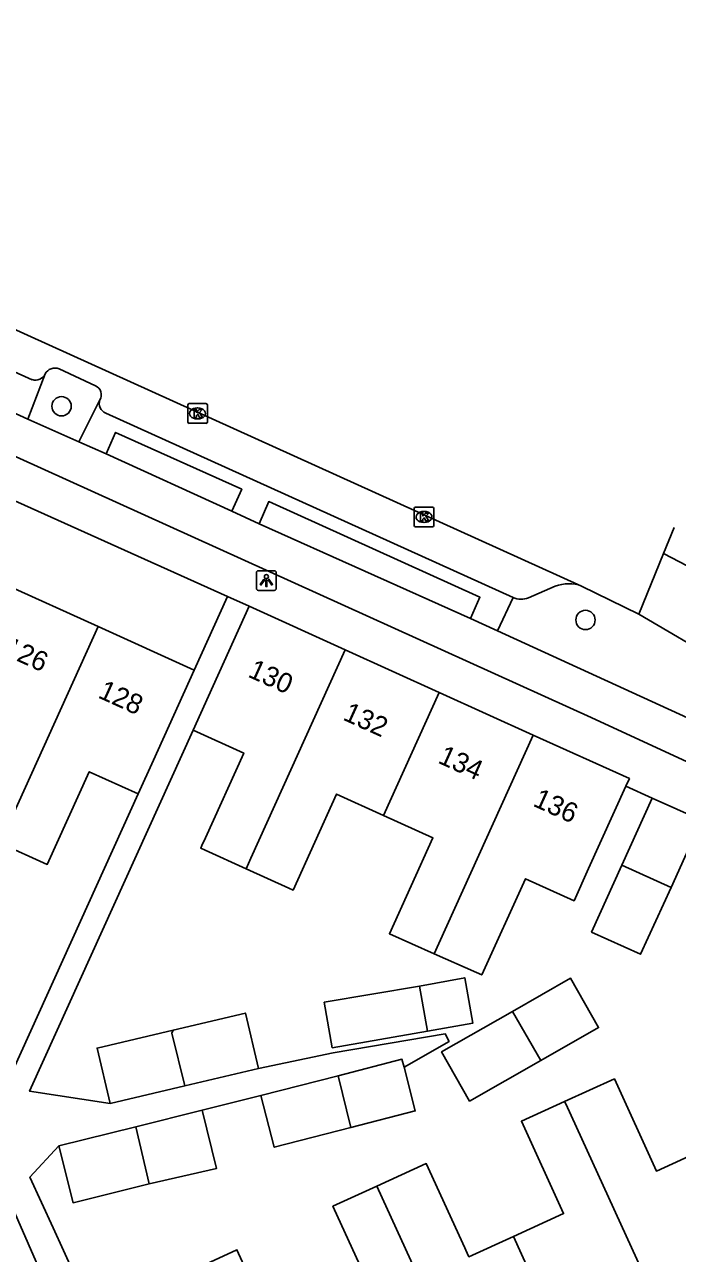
# Model space of a CAD drawing. Extents: x 161845 to 162341, y 381620 to 382158.
# Drawn here: x 162238.1 to 162271.1, y 381756.3 to 381818.5 of the extents above; entities that cross this region are included whole.
import ezdxf

# ---------------------------------------------------------------- set-up
doc = ezdxf.new("R2010")
doc.units = 0
for name, color, linetype in [('IMGEO_Boom', 7, 'Continuous'), ('IMGEO_Kolk', 7, 'Continuous'), ('IMGEO_Lichtpunt', 7, 'Continuous'), ('IMGEO_Pand', 7, 'Continuous'), ('IMGEO_Pand_nummerreeks', 7, 'Continuous'), ('IMGEO_Parkeervlak_open', 7, 'Continuous'), ('IMGEO_Rijbaan_lokaal_gesloten', 7, 'Continuous'), ('IMGEO_Voetpad_gesloten', 7, 'Continuous'), ('IMGEO_Voetpad_open', 7, 'Continuous')]:
    doc.layers.add(name, color=color, linetype=linetype)

msp = doc.modelspace()

# ---------------------------------------------------------------- linework, layer by layer
at = {"layer": 'IMGEO_Boom'}
for centre in [(162239.935, 381799.186), (162266.46, 381788.366)]:
    msp.add_circle(centre, 0.489, dxfattribs=at)
at = {"layer": 'IMGEO_Kolk'}
for p, q in [((162246.321, 381798.395), (162246.321, 381799.247)), ((162246.396, 381799.321), (162247.248, 381799.321)), ((162247.322, 381799.247), (162247.322, 381798.395)), ((162246.809, 381799.101), (162246.834, 381799.101)), ((162247.248, 381798.321), (162246.396, 381798.321)), ((162246.832, 381798.541), (162246.807, 381798.541)), ((162257.784, 381793.154), (162257.784, 381794.006)), ((162257.859, 381794.08), (162258.711, 381794.08)), ((162258.272, 381793.86), (162258.297, 381793.86)), ((162258.785, 381794.006), (162258.785, 381793.154)), ((162258.711, 381793.08), (162257.859, 381793.08)), ((162258.295, 381793.3), (162258.27, 381793.3))]:
    msp.add_line(p, q, dxfattribs=at)
for points in [[(162246.321, 381798.395), (162246.321, 381799.247)], [(162246.396, 381799.321), (162247.248, 381799.321)], [(162247.322, 381799.247), (162247.322, 381798.395)], [(162246.642, 381799.021), (162246.765, 381799.021), (162246.765, 381798.87), (162246.895, 381799.021), (162247.059, 381799.021), (162246.913, 381798.87), (162247.066, 381798.621), (162246.914, 381798.621), (162246.829, 381798.785), (162246.765, 381798.718), (162246.765, 381798.621), (162246.642, 381798.621), (162246.642, 381799.021)], [(162247.248, 381798.321), (162246.396, 381798.321)], [(162257.784, 381793.154), (162257.784, 381794.006)], [(162257.859, 381794.08), (162258.711, 381794.08)], [(162258.105, 381793.78), (162258.228, 381793.78), (162258.228, 381793.629), (162258.358, 381793.78), (162258.522, 381793.78), (162258.376, 381793.629), (162258.529, 381793.38), (162258.377, 381793.38), (162258.292, 381793.544), (162258.228, 381793.477), (162258.228, 381793.38), (162258.105, 381793.38), (162258.105, 381793.78)], [(162258.785, 381794.006), (162258.785, 381793.154)], [(162258.711, 381793.08), (162257.859, 381793.08)]]:
    msp.add_lwpolyline(points, dxfattribs=at)
for centre, start, end in [((162246.398, 381799.245), 91.55205, 178.44795), ((162246.398, 381799.245), 91.55205, 178.44795), ((162247.246, 381799.245), 1.55205, 88.44795), ((162247.246, 381799.245), 1.55205, 88.44795), ((162246.398, 381798.397), 181.55205, 268.44795), ((162246.398, 381798.397), 181.55205, 268.44795), ((162247.246, 381798.397), 271.55205, 358.44795), ((162247.246, 381798.397), 271.55205, 358.44795), ((162257.861, 381794.004), 91.55205, 178.44795), ((162257.861, 381794.004), 91.55205, 178.44795), ((162258.709, 381794.004), 1.55205, 88.44795), ((162258.709, 381794.004), 1.55205, 88.44795), ((162257.861, 381793.156), 181.55205, 268.44795), ((162257.861, 381793.156), 181.55205, 268.44795), ((162258.709, 381793.156), 271.55205, 358.44795), ((162258.709, 381793.156), 271.55205, 358.44795)]:
    msp.add_arc(centre, 0.0765, start, end, dxfattribs=at)
for centre, major_axis, ratio, start_param, end_param in [((162246.808, 381798.821), (-0.387, 0.002), 0.722429, 4.712389, 7.853982), ((162246.833, 381798.821), (-0.39, 0.002), 0.717154, 1.570796, 4.712389), ((162258.271, 381793.58), (-0.387, 0.002), 0.722429, 4.712389, 7.853982), ((162258.296, 381793.58), (-0.39, 0.002), 0.717154, 1.570796, 4.712389)]:
    msp.add_ellipse(centre, major_axis=major_axis, ratio=ratio, start_param=start_param, end_param=end_param, dxfattribs=at)
at = {"layer": 'IMGEO_Lichtpunt'}
for p, q in [((162249.806, 381790.763), (162249.806, 381789.956)), ((162249.806, 381790.763), (162249.806, 381789.956)), ((162250.708, 381790.858), (162249.9, 381790.858)), ((162250.708, 381790.858), (162249.9, 381790.858)), ((162250.802, 381789.956), (162250.802, 381790.763)), ((162250.802, 381789.956), (162250.802, 381790.763)), ((162249.9, 381789.862), (162250.708, 381789.862)), ((162249.9, 381789.862), (162250.708, 381789.862))]:
    msp.add_line(p, q, dxfattribs=at)
for points in [[(162250.18, 381790.427), (162250.219, 381790.399), (162250.031, 381790.137), (162249.993, 381790.164), (162250.18, 381790.427)], [(162250.282, 381790.379), (162250.329, 381790.379), (162250.329, 381790.057), (162250.282, 381790.057), (162250.282, 381790.379)], [(162250.392, 381790.399), (162250.43, 381790.426), (162250.617, 381790.164), (162250.578, 381790.136), (162250.392, 381790.399)]]:
    msp.add_lwpolyline(points, dxfattribs=at)
msp.add_circle((162250.305, 381790.561), 0.0994, dxfattribs=at)
for centre, start, end in [((162249.9, 381790.763), 90, 180), ((162249.9, 381790.763), 90, 180), ((162250.708, 381790.763), 0, 90), ((162250.708, 381790.763), 0, 90), ((162249.9, 381789.956), 180, 270), ((162249.9, 381789.956), 180, 270), ((162250.708, 381789.956), 270, 0), ((162250.708, 381789.956), 270, 360)]:
    msp.add_arc(centre, 0.0946, start, end, dxfattribs=at)
at = {"layer": 'IMGEO_Pand'}
for points in [[(162237.017, 381790.193), (162241.781, 381788.034)], [(162249.437, 381789.06), (162247.374, 381784.506), (162246.596, 381782.789)], [(162249.437, 381789.06), (162254.302, 381786.856)], [(162236.818, 381777.077), (162241.781, 381788.034)], [(162241.781, 381788.034), (162246.655, 381785.826)], [(162254.302, 381786.856), (162249.523, 381776.303), (162249.283, 381775.773)], [(162254.302, 381786.856), (162259.06, 381784.7)], [(162246.655, 381785.826), (162244.592, 381781.272), (162243.815, 381779.558)], [(162256.237, 381778.47), (162259.06, 381784.7)], [(162259.06, 381784.7), (162263.818, 381782.544)], [(162246.596, 381782.789), (162249.163, 381781.626), (162247.222, 381777.34), (162247.044, 381776.947), (162246.984, 381776.814), (162247.214, 381776.71), (162249.283, 381775.773)], [(162263.818, 381782.544), (162259.038, 381771.993), (162258.797, 381771.462)], [(162263.818, 381782.544), (162268.684, 381780.34), (162268.511, 381779.959)], [(162236.818, 381777.077), (162239.212, 381775.993), (162241.336, 381780.681), (162243.815, 381779.558)], [(162258.797, 381771.462), (162260.937, 381770.522), (162261.213, 381770.397), (162263.421, 381775.27), (162265.882, 381774.155), (162266.621, 381775.786), (162268.511, 381779.959)], [(162249.283, 381775.773), (162251.439, 381774.796), (162251.655, 381774.698), (162253.853, 381779.55), (162256.237, 381778.47)], [(162269.84, 381779.353), (162268.303, 381775.962)], [(162269.84, 381779.353), (162272.328, 381778.227)], [(162256.237, 381778.47), (162258.735, 381777.338), (162256.537, 381772.487), (162258.797, 381771.462)], [(162270.79, 381774.833), (162272.328, 381778.227)], [(162268.303, 381775.962), (162266.766, 381772.568), (162269.254, 381771.442), (162270.79, 381774.833)], [(162268.303, 381775.962), (162270.79, 381774.833)], [(162258.47, 381767.554), (162260.749, 381767.95), (162260.348, 381770.253), (162258.058, 381769.831)], [(162264.196, 381766.066), (162267.124, 381767.737), (162265.702, 381770.228), (162262.758, 381768.547)], [(162258.058, 381769.831), (162253.237, 381769.016), (162253.637, 381766.713), (162258.47, 381767.554)], [(162258.058, 381769.831), (162258.47, 381767.554)], [(162249.903, 381765.665), (162249.24, 381768.468), (162245.582, 381767.604)], [(162262.758, 381768.547), (162259.173, 381766.501), (162260.595, 381764.01), (162264.196, 381766.066)], [(162264.196, 381766.066), (162262.758, 381768.547)], [(162245.582, 381767.604), (162241.734, 381766.694), (162242.397, 381763.891)], [(162246.181, 381764.785), (162245.513, 381767.451), (162245.582, 381767.604)], [(162249.903, 381765.665), (162246.181, 381764.785)], [(162257.274, 381765.731), (162257.171, 381766.129), (162253.943, 381765.298)], [(162254.584, 381762.675), (162257.845, 381763.515), (162257.274, 381765.731)], [(162250.026, 381764.288), (162253.943, 381765.298)], [(162253.943, 381765.298), (162254.584, 381762.675)], [(162272.292, 381761.495), (162270.053, 381760.473), (162267.923, 381765.137), (162265.401, 381763.985)], [(162246.181, 381764.785), (162242.397, 381763.891)], [(162250.026, 381764.288), (162250.7, 381761.674), (162254.584, 381762.675)], [(162265.401, 381763.985), (162263.22, 381762.989), (162265.353, 381758.321), (162262.824, 381757.166)], [(162270.411, 381753.052), (162265.461, 381763.881), (162265.401, 381763.985)], [(162243.694, 381762.715), (162247.054, 381763.546)], [(162244.367, 381759.822), (162247.782, 381760.607), (162247.054, 381763.546)], [(162239.803, 381761.752), (162243.694, 381762.715)], [(162244.367, 381759.822), (162243.694, 381762.715)], [(162239.803, 381761.752), (162240.516, 381758.869), (162244.367, 381759.822)], [(162262.824, 381757.166), (162260.558, 381756.131), (162260.528, 381756.197), (162260.348, 381756.591), (162258.403, 381760.85), (162255.892, 381759.703)], [(162255.892, 381759.703), (162253.676, 381758.691), (162255.794, 381754.054), (162253.262, 381752.897)], [(162255.892, 381759.703), (162260.328, 381750), (162260.94, 381748.66)], [(162262.824, 381757.166), (162265.676, 381750.857)], [(162253.262, 381752.897), (162250.942, 381751.838), (162248.816, 381756.492), (162248.557, 381756.374), (162246.389, 381755.377)]]:
    msp.add_lwpolyline(points, dxfattribs=at)
at = {"layer": 'IMGEO_Parkeervlak_open'}
for points in [[(162241.652, 381800.215), (162239.807, 381801.071)], [(162263.572, 381789.489), (162264.932, 381790.07)]]:
    msp.add_lwpolyline(points, dxfattribs=at)
for centre, radius, start, end in [((162239.588, 381800.582), 0.536, 65.9133, 153.73669), ((162241.454, 381799.759), 0.497, 329.20142, 66.55126), ((162265.616, 381788.377), 1.826, 69.19088, 112.01259), ((162263.205, 381790.441), 1.02, 246.40912, 291.07766)]:
    msp.add_arc(centre, radius, start, end, dxfattribs=at)
at = {"layer": 'IMGEO_Rijbaan_lokaal_gesloten'}
for points in [[(162204.044, 381818.258), (162266.265, 381790.084)], [(162270.414, 381791.728), (162270.956, 381793.049)], [(162269.159, 381788.667), (162270.414, 381791.728)], [(162270.414, 381791.728), (162278.312, 381787.616)], [(162266.265, 381790.084), (162269.159, 381788.667)], [(162269.159, 381788.667), (162273.356, 381786.194)]]:
    msp.add_lwpolyline(points, dxfattribs=at)
at = {"layer": 'IMGEO_Voetpad_gesloten'}
for points in [[(162289.497, 381752.523), (162284.268, 381764.473), (162282.076, 381768.974), (162280.091, 381772.447), (162277.759, 381775.733), (162275.072, 381778.709), (162271.828, 381781.089), (162266.754, 381783.434), (162197.313, 381814.891), (162168.761, 381826.912), (162165.238, 381828.801), (162160.086, 381831.935), (162154.18, 381835.7), (162147.552, 381840.181), (162140.263, 381845.513), (162134.882, 381849.978)], [(162238.224, 381798.531), (162236.83, 381799.175)], [(162238.224, 381798.531), (162240.809, 381797.385)], [(162242.2, 381796.772), (162240.809, 381797.385)], [(162242.2, 381796.772), (162248.548, 381793.881)], [(162249.933, 381793.235), (162248.548, 381793.881)], [(162249.933, 381793.235), (162260.633, 381788.438)], [(162262.003, 381787.815), (162260.633, 381788.438)], [(162273.356, 381786.194), (162271.63, 381783.405), (162262.003, 381787.815)]]:
    msp.add_lwpolyline(points, dxfattribs=at)
at = {"layer": 'IMGEO_Voetpad_open'}
for points in [[(162228.374, 381805.071), (162238.449, 381800.531)], [(162219.499, 381802.515), (162226.946, 381799.168), (162248.332, 381789.557)], [(162239.108, 381800.819), (162238.224, 381798.531)], [(162240.809, 381797.385), (162241.881, 381799.505)], [(162262.797, 381789.506), (162242.174, 381798.84)], [(162248.548, 381793.881), (162249.055, 381794.988), (162242.674, 381797.863), (162242.2, 381796.772)], [(162260.633, 381788.438), (162261.118, 381789.513), (162250.429, 381794.356), (162249.933, 381793.235)], [(162246.655, 381785.826), (162248.332, 381789.557)], [(162248.332, 381789.557), (162249.437, 381789.06)], [(162262.003, 381787.815), (162262.797, 381789.506)], [(162242.397, 381763.891), (162238.316, 381764.513), (162239.716, 381767.603), (162246.596, 381782.789)], [(162268.511, 381779.959), (162269.84, 381779.353)], [(162243.815, 381779.558), (162237.08, 381764.702), (162236.512, 381763.449), (162235, 381764.156)], [(162257.274, 381765.731), (162259.558, 381767.031), (162259.358, 381767.416), (162253.69, 381766.464), (162249.903, 381765.665)], [(162247.054, 381763.546), (162250.026, 381764.288)], [(162243.697, 381748.424), (162239.506, 381757.601), (162238.334, 381760.167), (162239.803, 381761.752)], [(162237.082, 381759.473), (162238.889, 381755.337)]]:
    msp.add_lwpolyline(points, dxfattribs=at)
for centre, radius, start, end in [((162238.611, 381801.059), 0.552, 252.9511, 334.26204), ((162242.351, 381799.315), 0.507, 158.00838, 249.54834)]:
    msp.add_arc(centre, radius, start, end, dxfattribs=at)

# ---------------------------------------------------------------- texts
at = {"layer": 'IMGEO_Pand_nummerreeks'}
for s, rotation, p in [('126', 335.62652, (162236.927, 381786.633)), ('130', 335.62638, (162249.32, 381785.512)), ('128', 335.62652, (162241.732, 381784.456)), ('132', 335.62638, (162254.127, 381783.334)), ('134', 335.62638, (162258.94, 381781.154)), ('136', 335.62638, (162263.751, 381778.974))]:
    msp.add_text(s, height=1, rotation=rotation, dxfattribs=at).set_placement(p)

doc.saveas('drawing.dxf')
